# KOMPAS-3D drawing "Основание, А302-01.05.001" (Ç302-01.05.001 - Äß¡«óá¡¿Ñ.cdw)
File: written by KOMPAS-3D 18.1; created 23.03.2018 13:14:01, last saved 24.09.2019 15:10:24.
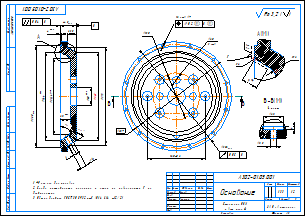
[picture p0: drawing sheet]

Sheet 1: A3, landscape

Document properties: Полное имя файла: D:\Мембранные насосы\Мембранный электропривод\А302-00.00.000 - ASTRA-302 (МЭ200)\3Д ПВХ\А302-01.05.001 - Основание.cdw; Масса: 1.33086

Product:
- Part/product: Основание  | designation А302-01.05.001
    Масса: 1.33086
    Раздел спецификации: Детали
    Форматы листов документа: A3
    source file: \\192.168.87.28\Konstructor_doc\Мембранные насосы\Мембранный электропривод\А302-00.00.000 - ASTRA-302 (МЭ200)\3Д ПВХ\А302-01.05.001 - Основание.cdw

Title block, sheet 1: Наименование: Основание; designation: А302-01.05.001; Масса: 1,33; scale: 1:2; Количество листов документа: 1; organisation: ЗАО «Астерион»; Форматы листов документа: A3; stored path: \\192.168.87.28\Konstructor_doc\Мембранные насосы\Мембранный электропривод\А302-00.00.000 - ASTRA-302 (МЭ200)\Чертежи\А302-00.05.001 - Основание.cdw; Разработал: Милов; Т. контр.: Лучихин

Views: Вид 1, Местный разрез 1, Вид:3, Проекционный вид 2, Выносной элемент 3, Разрез Б-Б, Выносной элемент А, Выносной элемент
Referenced files in \\192.168.87.28\Konstructor_doc\Мембранные насосы\Мембранный электропривод\А302-00.00.000 - ASTRA-302 (МЭ200)\3Д ПВХ\: А302-01.05.001 - Основание.m3d
Referenced files in Z:\Мембранные насосы\Мембранный электропривод\А302-00.00.000 - ASTRA-302 (МЭ200)\3Д\: А302-00.05.001 - Основание.m3d
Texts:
  Стержень ПВХ
  цвет серый
  Ra 3,2
  Ra 3,2 ( )
Dimensions and other numbers on the sheet: 16; 9; 50; 4; 23,5; 44,5; 245; 272; 28; 280; 211,67; 244; 0,04; 302; 0,05; 20; 3 отв.; 130; 160±0,2; 287; 12 отв.; 7; 6; 12; 2,5; 15; 6 мест; 8,5; 1:2; 1; 1,33

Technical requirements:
  *Размеры для справок.
  Следы инструмента, царапины и риски на поверхности  Г  не
  допускаются.
  Общие допуски ГОСТ 30893.2-mK (H14, h14,  t2/2).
